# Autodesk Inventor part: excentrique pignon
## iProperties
Shininess: 20.0
Angle Display Precision: 2
Document Length Units: 11269
Document Angle Units: 11279
Document Time Units: 11290
Document Mass Units: 11283
Document Length Units Precision: 3
Document Angle Units Precision: 2
Compacted: True
Created: 2009-07
Part Number: excentrique pignon
Material: Par défaut
Document SubType Name: Modélisation
Designer: EL
Density: 1 g/cm^3
Density: 0.0
Volumn: 0.0
Area: 0.0
PropertySet Name: Model Information
Control State: 0
Master: False
Checked Out: False
Author: EL
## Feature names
1. Extrusion1
2. Extrusion2
3. Extrusion3
4. Extrusion4
5. Extrusion5
6. Extrusion6
